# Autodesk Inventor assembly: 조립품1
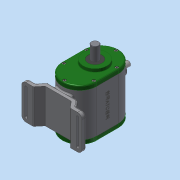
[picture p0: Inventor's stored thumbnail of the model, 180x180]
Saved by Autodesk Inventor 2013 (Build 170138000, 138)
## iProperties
Created: 2018-07
Part Number: 조립품1
Document SubType Name: Assembly
Designer: dgall
Author: dgall
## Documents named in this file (14)
- C:\Users\dgall\Desktop\380707V1002\조립품1.iam
- C:\Users\dgall\Desktop\380707V1002\본체.ipt
- C:\Users\dgall\Desktop\380707V1002\가변부품.ipt
- C:\Users\dgall\Desktop\380707V1002\부시.ipt
- C:\Users\dgall\Desktop\380707V1002\슬라이더.ipt
- C:\Users\dgall\Desktop\380707V1002\뒤커버.ipt
- C:\Users\dgall\Desktop\380707V1002\베어링 608.ipt
- C:\Users\dgall\Desktop\380707V1002\볼트 M4.ipt
- C:\Users\dgall\Desktop\380707V1002\오일 실 8 22 7.ipt
- C:\Users\dgall\Desktop\380707V1002\메인축.ipt
- C:\Users\dgall\Desktop\380707V1002\베어링 6003.ipt
- C:\Users\dgall\Desktop\380707V1002\서브축.ipt
- C:\Users\dgall\Desktop\380707V1002\앞커버.ipt
- C:\Users\dgall\Desktop\380707V1002\오일 실 17 32 8.ipt
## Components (1 placed, 1 different names)
1. 가변부품:1
